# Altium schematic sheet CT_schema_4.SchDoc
size 522 x 483 mm
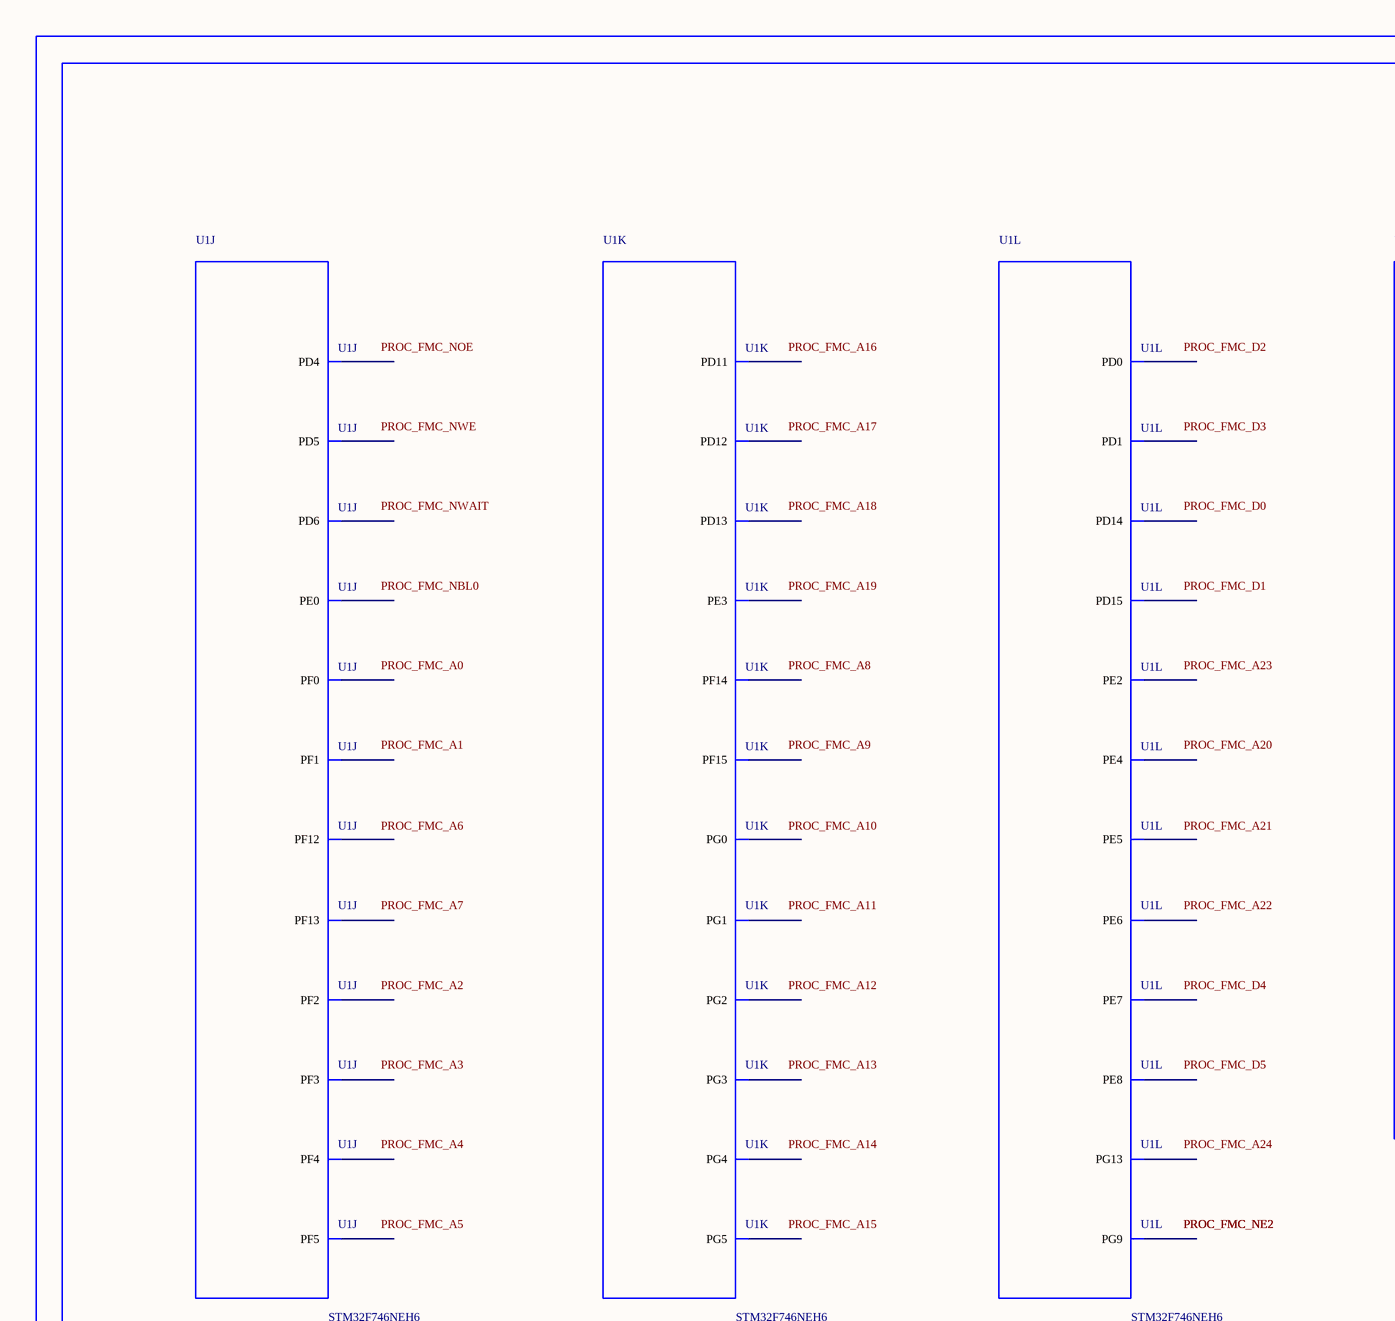
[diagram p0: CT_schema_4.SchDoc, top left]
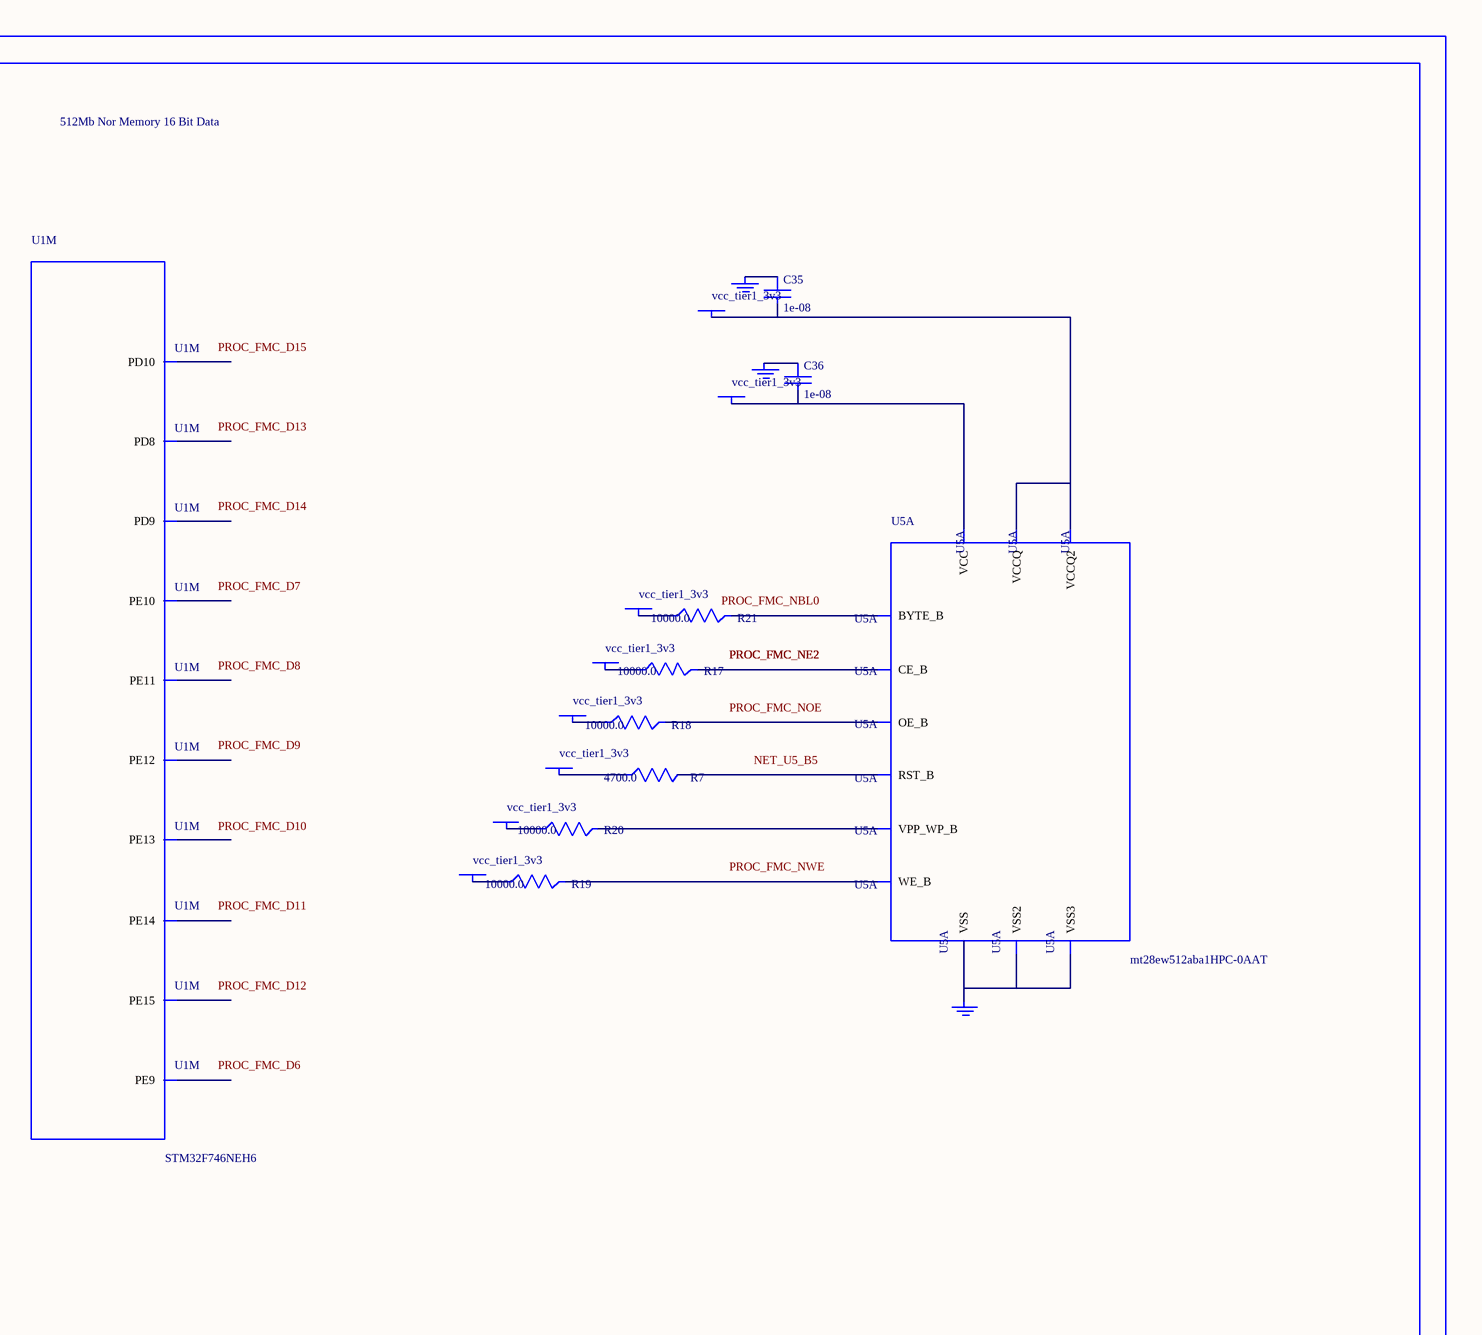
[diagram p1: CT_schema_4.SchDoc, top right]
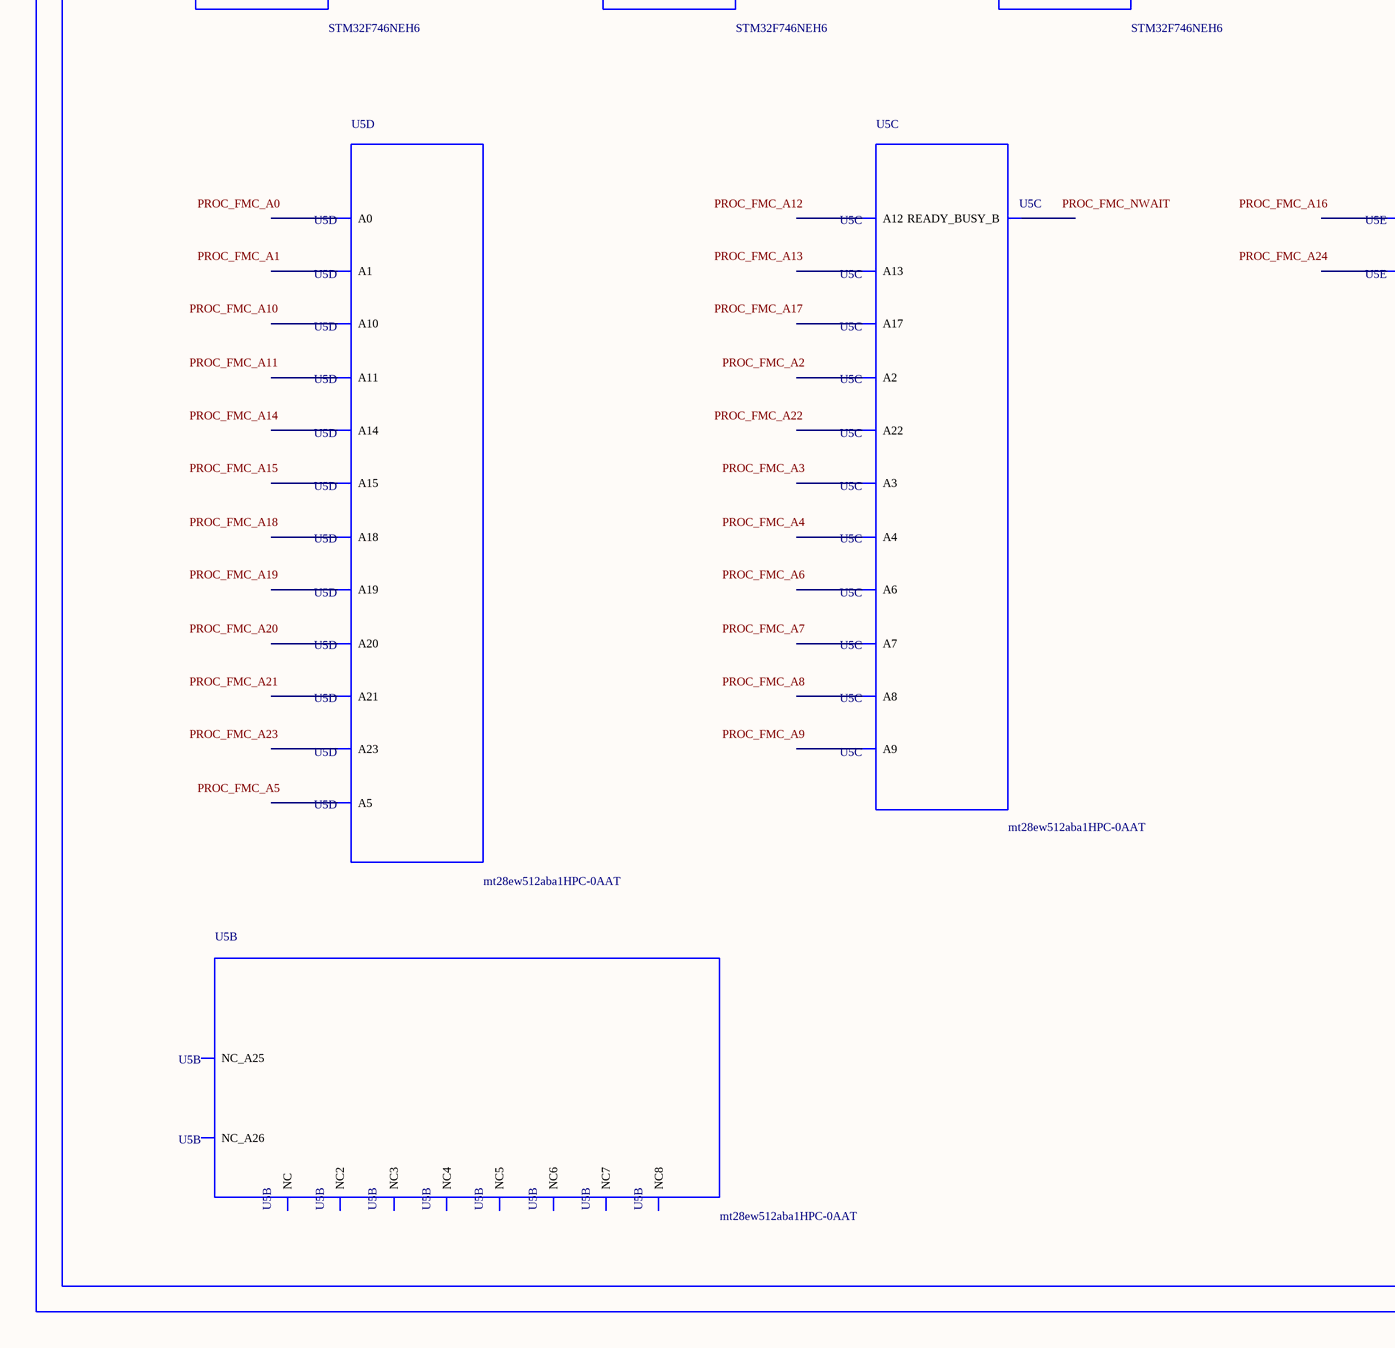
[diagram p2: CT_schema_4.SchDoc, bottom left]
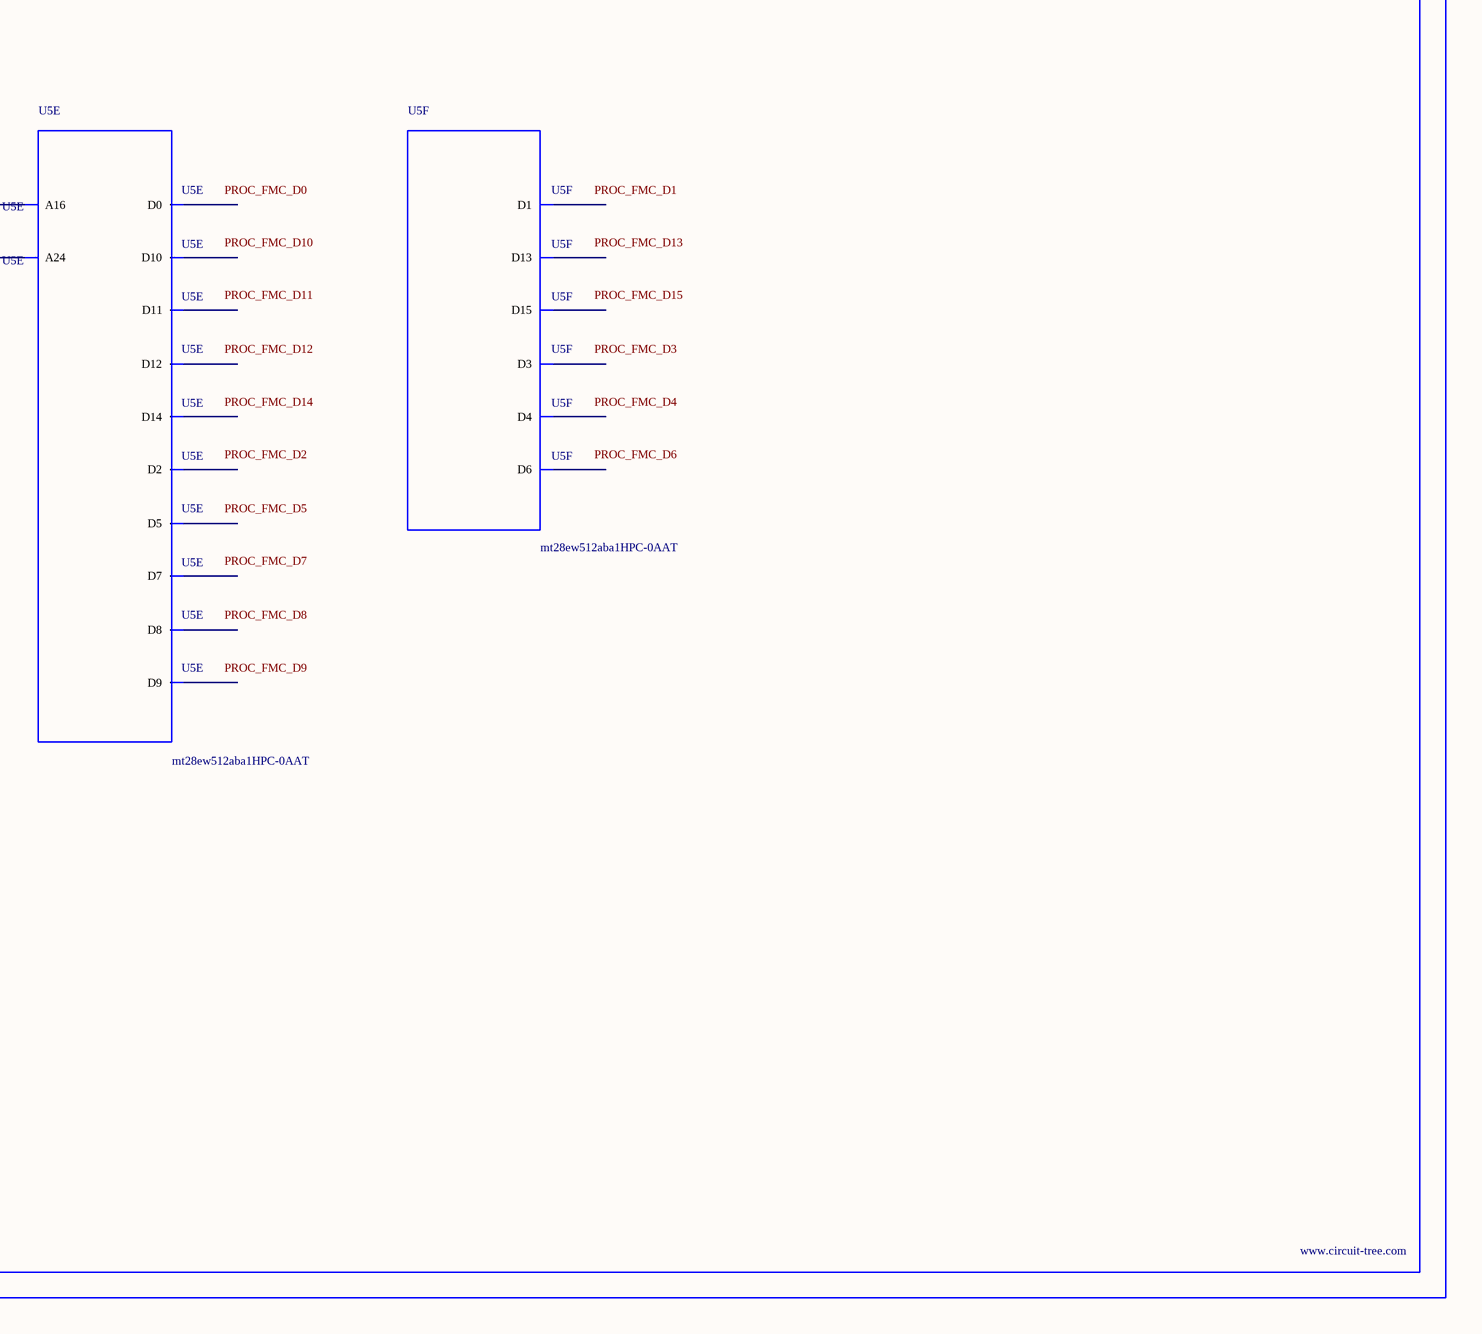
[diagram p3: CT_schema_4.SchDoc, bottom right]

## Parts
BORDER3  (no value)
C35  1e-08  [C0402]
C36  1e-08  [C0402]
GND_INSTANCE_3_0  (no value)
GND_INSTANCE_3_1  (no value)
GND_INSTANCE_3_2  (no value)
POWER_INSTANCE_3_0  vcc_tier1_3v3
POWER_INSTANCE_3_1  vcc_tier1_3v3
POWER_INSTANCE_3_2  vcc_tier1_3v3
POWER_INSTANCE_3_3  vcc_tier1_3v3
POWER_INSTANCE_3_4  vcc_tier1_3v3
POWER_INSTANCE_3_5  vcc_tier1_3v3
POWER_INSTANCE_3_6  vcc_tier1_3v3
POWER_INSTANCE_3_7  vcc_tier1_3v3
R7  4700.0  [R0603]
R17  10000.0  [R0603]
R18  10000.0  [R0603]
R19  10000.0  [R0603]
R20  10000.0  [R0603]
R21  10000.0  [R0603]
U1  STM32F746NEH6  [TFBGA216]  (parts J,K,L,M of 14)
U5  mt28ew512aba1HPC-0AAT  [LBGA-64]  (parts A,B,C,D,E,F of 6)

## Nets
NetC35_1: C35.1 GND_INSTANCE_3_0.0(GND)
NetC35_2: C35.2 POWER_INSTANCE_3_0.0(PWR) U5.D8(VCCQ) U5.F1(VCCQ2)
NetC36_1: C36.1 GND_INSTANCE_3_1.0(GND)
NetC36_2: C36.2 POWER_INSTANCE_3_1.0(PWR) U5.G5(VCC)
NetGND_INSTANCE_3_2_0: GND_INSTANCE_3_2.0(GND) U5.E8(VSS) U5.H2(VSS2) U5.H7(VSS3)
NetPOWER_INSTANCE_3_2_0: POWER_INSTANCE_3_2.0(PWR) R17.1
NetPOWER_INSTANCE_3_3_0: POWER_INSTANCE_3_3.0(PWR) R18.1
NetPOWER_INSTANCE_3_4_0: POWER_INSTANCE_3_4.0(PWR) R19.1
NetPOWER_INSTANCE_3_5_0: POWER_INSTANCE_3_5.0(PWR) R20.1
NetPOWER_INSTANCE_3_6_0: POWER_INSTANCE_3_6.0(PWR) R21.1
NetPOWER_INSTANCE_3_7_0: POWER_INSTANCE_3_7.0(PWR) R7.1
NetR7_2: R7.2 U5.B5(RST_B)
NetR17_2: R17.2 U5.F2(CE_B)
NetR18_2: R18.2 U5.G2(OE_B)
NetR19_2: R19.2 U5.A5(WE_B)
NetR20_2: R20.2 U5.B4(VPP_WP_B)
NetR21_2: R21.2 U5.F7(BYTE_B)

Not connected (* = marked no-connect by the designer): U1 A1(PE4) A2(PE3) A3(PE2) A6(PE0) B1(PE5) B2(PE6) B3(PG13) B11(PD6) B12(PD0) C10(PD5) C12(PD1) D2(PF0) D9(PG9) D11(PD4) E2(PF1) G2(PF2) H2(PF3) J2(PF4) K3(PF5) K13(PD15) K15(PD10) L12(PD14) L14(PD9) L15(PD8) M6(PF12) M7(PG1) M8(PF15) M10(PD12) M11(PD13) M12(PG3) M13(PG2) N6(PF13) N7(PG0) N9(PE8) N10(PD11) N11(PG5) N12(PG4) P6(PF14) P9(PE9) P10(PE11) P11(PE14) R8(PE7) R9(PE10) R10(PE12) R11(PE15) R12(PE13); U5 A1(NC) A2(A3) A3(A7) A4(READY_BUSY_B) A6(A9) A7(A13) A8(NC2) B1(NC_A26) B2(A4) B3(A17) B6(A8) B7(A12) B8(A22) C1(NC3) C2(A2) C3(A6) C4(A18) C5(A21) C6(A10) C7(A14) C8(A23) D1(NC4) D2(A1) D3(A5) D4(A20) D5(A19) D6(A11) D7(A15) E1(NC5) E2(A0) E3(D0) E4(D2) E5(D5) E6(D7) E7(A16) F3(D8) F4(D10) F5(D12) F6(D14) F8(A24) G1(NC6) G3(D9) G4(D11) G6(D13) G7(D15) G8(NC_A25) H1(NC7) H3(D1) H4(D3) H5(D4) H6(D6) H8(NC8)

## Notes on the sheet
- Labels drawn without touching a wire or pin: NET_U5_B5, PROC_FMC_A0, PROC_FMC_A1, PROC_FMC_A2, PROC_FMC_A3, PROC_FMC_A4, PROC_FMC_A5, PROC_FMC_A6, PROC_FMC_A7, PROC_FMC_A8, PROC_FMC_A9, PROC_FMC_A10, PROC_FMC_A11, PROC_FMC_A12, PROC_FMC_A13, PROC_FMC_A14, PROC_FMC_A15, PROC_FMC_A16, PROC_FMC_A17, PROC_FMC_A18, PROC_FMC_A19, PROC_FMC_A20, PROC_FMC_A21, PROC_FMC_A22, PROC_FMC_A23, PROC_FMC_A24, PROC_FMC_D0, PROC_FMC_D1, PROC_FMC_D2, PROC_FMC_D3, PROC_FMC_D4, PROC_FMC_D5, PROC_FMC_D6, PROC_FMC_D7, PROC_FMC_D8, PROC_FMC_D9, PROC_FMC_D10, PROC_FMC_D11, PROC_FMC_D12, PROC_FMC_D13, PROC_FMC_D14, PROC_FMC_D15, PROC_FMC_NBL0, PROC_FMC_NOE, PROC_FMC_NWAIT, PROC_FMC_NWE

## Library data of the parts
BORDER3 = BORDER_PAGE3
C35 C36 = C0402C103K3RAC
GND_INSTANCE_3_0-GND_INSTANCE_3_2 = GND
POWER_INSTANCE_3_0-POWER_INSTANCE_3_7 = PWR
R7 = RC0603JR-074K7L
R17-R21 = RC0603JR-0710KL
